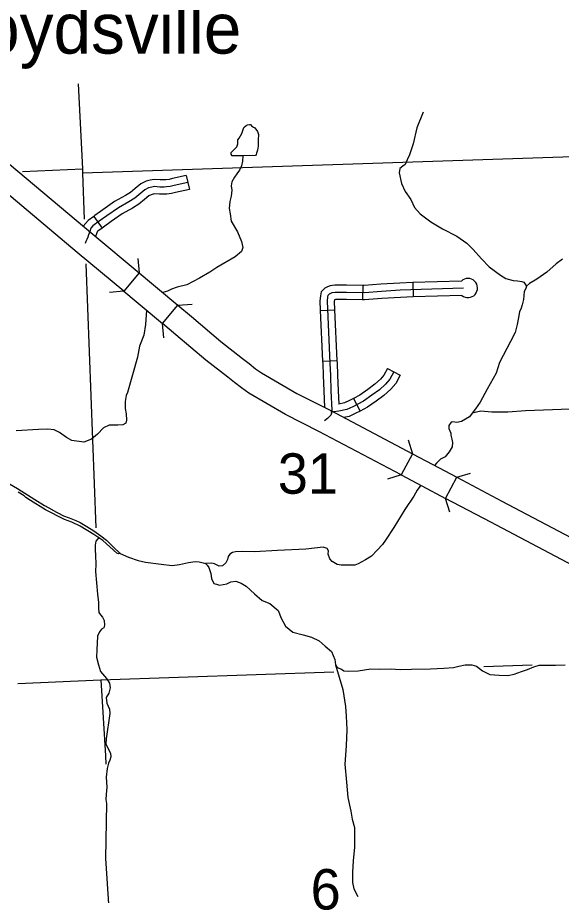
# Model space of a CAD drawing. Extents: x -5566 to 1759129, y -3726 to 731467.
# Drawn here: x -4657.8 to -4614.7, y 261.2 to 330.8 of the extents above; entities that cross this region are included whole.
import ezdxf

# ---------------------------------------------------------------- set-up
doc = ezdxf.new("R2010")
doc.units = 0
doc.layers.add('Default', color=7, linetype='Continuous')

msp = doc.modelspace()

# ---------------------------------------------------------------- linework, layer by layer
at = {"layer": 'Default'}
for p, q in [((-4644.471, 318.303), (-4644.22, 317.191)), ((-4651.807, 315.061), (-4651.133, 314.142)), ((-4630.479, 309.585), (-4630.494, 308.446)), ((-4626.502, 309.81), (-4626.466, 308.671)), ((-4633.838, 307.595), (-4632.7, 307.646)), ((-4633.659, 303.589), (-4632.521, 303.64)), ((-4628.501, 303.008), (-4627.5, 302.464)), ((-4631.212, 300.628), (-4630.685, 299.619))]:
    msp.add_line(p, q, dxfattribs=at)
for points in [[(-4653.033, 325.568), (-4652.708, 318.841), (-4652.694, 318.485), (-4652.558, 314.851)], [(-4625.686, 323.321), (-4626.173, 322.099), (-4626.469, 320.823), (-4626.756, 319.959), (-4626.954, 319.556), (-4627.122, 319.176), (-4627.285, 319.049), (-4627.521, 318.865), (-4627.577, 318.52), (-4627.409, 317.665), (-4627.112, 317.028), (-4626.672, 316.403), (-4626.376, 315.781), (-4625.917, 315.272), (-4625.067, 314.632), (-4624.143, 314.086), (-4623.021, 313.494), (-4622.227, 312.943), (-4621.73, 312.443), (-4621.058, 311.698), (-4620.436, 311.061), (-4619.547, 310.407), (-4619.13, 310.148), (-4618.554, 309.986), (-4618.202, 309.959), (-4617.866, 309.887), (-4617.704, 309.852), (-4617.475, 309.523)], [(-4640.457, 320.586), (-4640.378, 320.809), (-4640.391, 320.954), (-4640.391, 321.125), (-4640.286, 321.269), (-4640.049, 321.637), (-4639.892, 322.11), (-4639.721, 322.281), (-4639.603, 322.321), (-4639.458, 322.36), (-4639.366, 322.36), (-4639.288, 322.255), (-4639.13, 322.137), (-4639.038, 322.084), (-4638.828, 321.795), (-4638.749, 321.558), (-4638.762, 321.138)], [(-4638.762, 321.138), (-4638.762, 320.638), (-4638.828, 320.323), (-4638.893, 320.073), (-4638.92, 319.968), (-4638.985, 319.902), (-4639.971, 319.876), (-4640.825, 319.863), (-4640.917, 320.008), (-4640.917, 320.139), (-4640.68, 320.362), (-4640.457, 320.586)], [(-4613.817, 319.783), (-4652.694, 318.485)], [(-4639.971, 319.876), (-4640.007, 319.443), (-4640.092, 319.074), (-4640.247, 318.741), (-4640.464, 318.428), (-4640.645, 318.185), (-4640.851, 317.812), (-4640.908, 317.498), (-4640.865, 317.141), (-4640.916, 316.659), (-4641.022, 316.236), (-4641.055, 315.694), (-4640.979, 315.262), (-4640.912, 314.693), (-4640.418, 313.834), (-4640.086, 313.061), (-4639.986, 312.6), (-4640.096, 312.283), (-4640.597, 311.869), (-4642.053, 311.001), (-4642.602, 310.646), (-4643.412, 310.167), (-4644.426, 309.642), (-4645.2, 309.447), (-4645.643, 309.301), (-4645.956, 309.145), (-4646.336, 309.026)], [(-4658.494, 319.208), (-4651.889, 313.649), (-4648.215, 310.59)], [(-4657.461, 318.617), (-4652.708, 318.841)], [(-4644.471, 318.303), (-4645.557, 318.058), (-4645.836, 317.996), (-4646.088, 317.965), (-4646.237, 317.96), (-4646.538, 317.962), (-4647.002, 317.994), (-4647.32, 317.944), (-4647.659, 317.854), (-4648.073, 317.639), (-4648.513, 317.271)], [(-4648.215, 310.59), (-4649.43, 309.131), (-4653.107, 312.194), (-4659.717, 317.756)], [(-4644.346, 317.747), (-4645.433, 317.502), (-4645.739, 317.434), (-4646.044, 317.396), (-4646.23, 317.391), (-4646.56, 317.393), (-4646.976, 317.422), (-4647.203, 317.386), (-4647.453, 317.32), (-4647.755, 317.162), (-4648.55, 316.498), (-4649.011, 316.218), (-4649.85, 315.749), (-4650.757, 315.119), (-4651.374, 314.672), (-4651.871, 314.308), (-4652.026, 314.129), (-4652.122, 313.878), (-4652.211, 313.591), (-4652.271, 313.429), (-4652.347, 313.222), (-4652.426, 313.065), (-4652.498, 312.922)], [(-4648.513, 317.271), (-4648.882, 316.963), (-4649.298, 316.71), (-4650.153, 316.233), (-4651.086, 315.583), (-4651.709, 315.132), (-4651.807, 315.061)], [(-4644.22, 317.191), (-4645.309, 316.946), (-4645.642, 316.872), (-4646, 316.828), (-4646.223, 316.821), (-4646.582, 316.823), (-4646.951, 316.849), (-4647.085, 316.828), (-4647.246, 316.785), (-4647.437, 316.686), (-4647.783, 316.397)], [(-4647.783, 316.397), (-4648.217, 316.034), (-4648.725, 315.726), (-4649.548, 315.266), (-4650.427, 314.654), (-4651.039, 314.211), (-4651.133, 314.142)], [(-4651.807, 315.061), (-4652.259, 314.729), (-4652.644, 314.285)], [(-4651.133, 314.142), (-4651.482, 313.886), (-4651.53, 313.832), (-4651.583, 313.691), (-4651.657, 313.456)], [(-4652.423, 311.288), (-4651.635, 290.355)], [(-4648.319, 311.724), (-4648.215, 310.59)], [(-4614.632, 311.665), (-4615.123, 311.303), (-4615.876, 310.652), (-4616.668, 310.09), (-4617.255, 309.729), (-4617.475, 309.523), (-4617.551, 309.333), (-4617.664, 309.101), (-4617.722, 308.483), (-4617.825, 308.057), (-4617.906, 307.796), (-4618.039, 307.494), (-4618.131, 307.044), (-4618.217, 306.477), (-4618.381, 305.858), (-4618.769, 305.134), (-4619.635, 303.464), (-4619.894, 302.637), (-4620.599, 301.372), (-4621.175, 300.322), (-4621.536, 299.813), (-4621.804, 299.453), (-4621.997, 299.165), (-4622.629, 298.797), (-4623.006, 298.718), (-4623.339, 298.77), (-4623.453, 298.744), (-4623.637, 298.489)], [(-4648.215, 310.59), (-4647.235, 309.773), (-4646.751, 309.375), (-4645.135, 308.017)], [(-4622.654, 309.934), (-4626.502, 309.81)], [(-4630.479, 309.585), (-4631.749, 309.602), (-4632.367, 309.609), (-4632.697, 309.602), (-4633.056, 309.565), (-4633.268, 309.476), (-4633.487, 309.373), (-4633.77, 309.071), (-4633.833, 308.755), (-4633.872, 308.356), (-4633.838, 307.595)], [(-4622.476, 309.369), (-4627.496, 309.208), (-4628.996, 309.117), (-4630.347, 309.014), (-4631.756, 309.033), (-4632.364, 309.04), (-4632.661, 309.033), (-4632.914, 309.007), (-4633.036, 308.956), (-4633.146, 308.904), (-4633.243, 308.8), (-4633.269, 308.671), (-4633.301, 308.341), (-4633.082, 303.426), (-4633.043, 302.456), (-4632.991, 301.241), (-4632.926, 299.702), (-4632.946, 299.449), (-4632.991, 299.307), (-4633.079, 299.207), (-4633.273, 299.046), (-4633.508, 298.841)], [(-4626.502, 309.81), (-4627.523, 309.777), (-4629.035, 309.686), (-4630.365, 309.584), (-4630.479, 309.585)], [(-4649.43, 309.131), (-4650.565, 309.028)], [(-4649.43, 309.131), (-4648.446, 308.31), (-4647.965, 307.915), (-4646.357, 306.563)], [(-4630.494, 308.446), (-4631.763, 308.463), (-4632.361, 308.47), (-4632.626, 308.464), (-4632.718, 308.455), (-4632.731, 308.326), (-4632.7, 307.646)], [(-4626.466, 308.671), (-4627.47, 308.639), (-4628.957, 308.549), (-4630.329, 308.444), (-4630.494, 308.446)], [(-4622.614, 308.795), (-4626.466, 308.671)], [(-4646.357, 306.563), (-4645.135, 308.017), (-4644.06, 307.113), (-4641.727, 305.146), (-4640.01, 303.798), (-4639.48, 303.384), (-4638.968, 302.986), (-4638.49, 302.648), (-4635.691, 301.027), (-4633.07, 299.684), (-4626.538, 296.241), (-4627.423, 294.562)], [(-4645.135, 308.017), (-4644, 308.115)], [(-4647.626, 307.63), (-4647.69, 306.499), (-4647.833, 305.648), (-4648.166, 304.771), (-4648.336, 303.888), (-4649.138, 301.1), (-4649.231, 300.864), (-4649.32, 300.389), (-4649.314, 299.825), (-4649.223, 299.409), (-4649.197, 298.899), (-4649.272, 298.66), (-4649.51, 298.53), (-4649.889, 298.516), (-4650.595, 298.513), (-4651.035, 298.292), (-4651.51, 297.802), (-4651.974, 297.404), (-4652.588, 297.161), (-4653.534, 297.294), (-4653.96, 297.515), (-4654.521, 297.93), (-4654.946, 298.128), (-4655.442, 298.19), (-4656.186, 298.17), (-4657.966, 298.048)], [(-4633.838, 307.595), (-4633.659, 303.589)], [(-4632.7, 307.646), (-4632.521, 303.64)], [(-4627.423, 294.562), (-4633.946, 297.999), (-4636.6, 299.359), (-4639.516, 301.049), (-4640.099, 301.461), (-4640.647, 301.887), (-4641.18, 302.303), (-4642.925, 303.673), (-4645.283, 305.661), (-4646.357, 306.563)], [(-4646.259, 305.428), (-4646.357, 306.563)], [(-4633.659, 303.589), (-4633.651, 303.402), (-4633.612, 302.433), (-4633.56, 301.217), (-4633.505, 299.906)], [(-4632.521, 303.64), (-4632.513, 303.451), (-4632.474, 302.48), (-4632.422, 301.265), (-4632.377, 300.183)], [(-4628.501, 303.008), (-4628.795, 302.467), (-4629.067, 302.153), (-4629.511, 301.755), (-4630.08, 301.335), (-4630.703, 300.895), (-4631.212, 300.628)], [(-4628.001, 302.736), (-4628.324, 302.141), (-4628.66, 301.753), (-4629.151, 301.313), (-4629.746, 300.873), (-4630.405, 300.408), (-4631.272, 299.955), (-4631.724, 299.735), (-4632.358, 299.606), (-4632.771, 299.567), (-4632.991, 299.548)], [(-4627.5, 302.464), (-4627.853, 301.815), (-4628.253, 301.352), (-4628.791, 300.871), (-4629.412, 300.412), (-4630.108, 299.92), (-4630.685, 299.619)], [(-4631.212, 300.628), (-4631.528, 300.464), (-4631.908, 300.279), (-4632.377, 300.183)], [(-4630.685, 299.619), (-4631.015, 299.446), (-4631.54, 299.191), (-4631.97, 299.104)], [(-4612.601, 299.823), (-4617.567, 299.637), (-4618.971, 299.542), (-4619.69, 299.525), (-4620.234, 299.525), (-4621.112, 299.615), (-4621.804, 299.453)], [(-4623.637, 298.489), (-4623.637, 298.244), (-4623.479, 297.875), (-4623.497, 297.717), (-4623.4, 297.405), (-4623.368, 297.139), (-4623.378, 296.785), (-4623.63, 296.384), (-4623.935, 296), (-4624.309, 295.815), (-4624.636, 295.487), (-4624.774, 295.311)], [(-4626.875, 297.329), (-4626.538, 296.241)], [(-4626.538, 296.241), (-4624.904, 295.38), (-4623.012, 294.377)], [(-4661.41, 295.616), (-4660.163, 294.801), (-4657.844, 293.485)], [(-4627.423, 294.562), (-4628.512, 294.225)], [(-4627.423, 294.562), (-4625.791, 293.702), (-4623.901, 292.699)], [(-4623.012, 294.377), (-4621.923, 294.711)], [(-4595.073, 281.248), (-4595.087, 279.35), (-4595.451, 279.352), (-4596.296, 279.328), (-4597.053, 279.371), (-4597.723, 279.461), (-4598.724, 279.631), (-4598.995, 279.743), (-4599.363, 279.865), (-4600.547, 280.405), (-4611.583, 286.139), (-4612.869, 286.86), (-4620.322, 290.802), (-4623.901, 292.699), (-4623.012, 294.377)], [(-4623.012, 294.377), (-4619.434, 292.48), (-4611.96, 288.528), (-4610.68, 287.81), (-4599.715, 282.112), (-4598.669, 281.635), (-4598.331, 281.523), (-4598.194, 281.466), (-4597.439, 281.338), (-4596.873, 281.263), (-4596.269, 281.228), (-4595.471, 281.251), (-4595.073, 281.248)], [(-4657.844, 293.485), (-4656.477, 292.616), (-4655.707, 292.139), (-4655.081, 291.779)], [(-4649.689, 288.317), (-4649.848, 288.309), (-4649.975, 288.36), (-4651.08, 289.351), (-4651.791, 289.834), (-4652.883, 290.507), (-4653.531, 290.812), (-4654.128, 291.015), (-4655.639, 291.803), (-4656.833, 292.527), (-4657.183, 292.779), (-4657.331, 292.888), (-4657.81, 293.187)], [(-4625.875, 293.746), (-4626.145, 293.359), (-4626.431, 292.869), (-4627.129, 291.815), (-4628.018, 290.388), (-4628.665, 289.389), (-4628.91, 289.037), (-4629.326, 288.58), (-4629.773, 288.114), (-4630.256, 287.83), (-4630.829, 287.52), (-4631.106, 287.403), (-4631.447, 287.399), (-4631.789, 287.409), (-4632.176, 287.403), (-4632.505, 287.459), (-4632.885, 287.705), (-4633.075, 287.911), (-4633.217, 288.272), (-4633.196, 288.532), (-4633.294, 288.719), (-4633.617, 288.822), (-4634.993, 288.681), (-4637.236, 288.569), (-4639.047, 288.458), (-4640.019, 288.484), (-4640.565, 288.449), (-4640.806, 288.402), (-4641.006, 288.273), (-4641.136, 288.085), (-4641.196, 287.847), (-4641.323, 287.591), (-4641.587, 287.345), (-4641.852, 287.313), (-4642.076, 287.426), (-4642.216, 287.513), (-4642.446, 287.566), (-4642.942, 287.533)], [(-4623.567, 291.611), (-4623.901, 292.699)], [(-4655.108, 291.795), (-4654.204, 291.32), (-4653.747, 291.168), (-4653.223, 290.951), (-4652.883, 290.774), (-4652.363, 290.469), (-4651.804, 290.113), (-4651.233, 289.719), (-4650.796, 289.374), (-4650.243, 288.818), (-4649.71, 288.324)], [(-4651.364, 289.614), (-4651.634, 289.315), (-4651.699, 289), (-4651.7, 288.619), (-4651.661, 288.155), (-4651.629, 287.493), (-4651.653, 286.906), (-4651.512, 285.112), (-4651.441, 284.429), (-4651.433, 283.994), (-4651.398, 283.653), (-4651.269, 283.452), (-4651.111, 283.267), (-4650.98, 283.005), (-4650.956, 282.634), (-4651.005, 282.424), (-4651.178, 282.313), (-4651.346, 282.116), (-4651.511, 281.77), (-4651.548, 280.684), (-4651.597, 280.104), (-4651.425, 279.486), (-4651.264, 278.98), (-4650.793, 278.401), (-4650.548, 278.031), (-4650.511, 277.661), (-4650.598, 277.241), (-4650.82, 276.908), (-4650.758, 276.451), (-4650.548, 275.97), (-4650.524, 275.649), (-4650.829, 273.617), (-4650.857, 273.218), (-4650.746, 272.983), (-4650.474, 272.502), (-4650.45, 272.205), (-4650.524, 271.946), (-4650.635, 271.699), (-4650.746, 271.28), (-4650.82, 270.576), (-4650.761, 269.784), (-4650.833, 269.214), (-4650.853, 268.817), (-4650.783, 268.503), (-4650.863, 264.146), (-4650.596, 260.146)], [(-4649.71, 288.324), (-4649.048, 288.03), (-4648.286, 287.776), (-4647.701, 287.651), (-4646.453, 287.476), (-4645.578, 287.383), (-4645.009, 287.445), (-4644.301, 287.6), (-4643.769, 287.695), (-4643.447, 287.659), (-4643.121, 287.594), (-4642.942, 287.533), (-4642.808, 287.401), (-4642.686, 287.219), (-4642.522, 286.753), (-4642.473, 286.339), (-4642.278, 285.951), (-4642.06, 285.896), (-4641.834, 285.808), (-4641.263, 285.913), (-4640.926, 286.074), (-4640.542, 286.14), (-4640.125, 285.973), (-4639.722, 285.728), (-4639.07, 285.119), (-4638.44, 284.606), (-4637.835, 284.363), (-4637.192, 283.807), (-4636.948, 283.207), (-4636.597, 282.564), (-4636.026, 282.074), (-4635.209, 281.887), (-4634.533, 281.689), (-4633.934, 281.394), (-4633.443, 280.973), (-4632.939, 280.564), (-4632.686, 279.915), (-4632.624, 279.483), (-4632.055, 277.528), (-4631.834, 276.2), (-4631.797, 275.426), (-4631.741, 274.357), (-4631.778, 273.067), (-4631.889, 271.613), (-4631.76, 270.201), (-4631.668, 268.984), (-4631.41, 267.878), (-4631.299, 267.252), (-4631.133, 266.606), (-4631.115, 265.851), (-4631.115, 265.027), (-4631.229, 263.953), (-4631.287, 263.043), (-4631.287, 262.221), (-4631.184, 261.72), (-4630.861, 261.117)], [(-4632.624, 279.483), (-4632.493, 279.272), (-4632.169, 279.154), (-4631.984, 279.019), (-4631.619, 278.986), (-4630.839, 279.021), (-4629.825, 279.168), (-4629.144, 279.15), (-4628.282, 279.176), (-4627.485, 279.131), (-4626.61, 279.156), (-4625.105, 279.167), (-4624.044, 279.221), (-4623.272, 279.287), (-4622.858, 279.386), (-4622.353, 279.495), (-4621.815, 279.5), (-4621.446, 279.383), (-4620.968, 279.032), (-4620.394, 278.742), (-4619.652, 278.686), (-4618.967, 278.65), (-4618.459, 278.753), (-4617.896, 278.97), (-4617.419, 279.126), (-4616.91, 279.344), (-4616.492, 279.467), (-4615.198, 279.458), (-4614.427, 279.484)], [(-4620.881, 279.367), (-4617.047, 279.501)], [(-4651.238, 278.299), (-4632.765, 278.949)], [(-4657.829, 278.025), (-4651.238, 278.299)], [(-4651.238, 278.299), (-4650.863, 272.275), (-4650.834, 271.613)]]:
    msp.add_lwpolyline(points, dxfattribs=at)
msp.add_arc((-4622.132, 309.382), 0.759, 230.60975, 133.42863, dxfattribs=at)

# ---------------------------------------------------------------- texts
for s, height, p in [('Boydsville', 4.0097, (-4664.237, 327.974)), ('31', 3.2048, (-4637.206, 293.066)), ('6', 3.208, (-4634.606, 260.088))]:
    msp.add_text(s, height=height, dxfattribs=at).set_placement(p)

doc.saveas('drawing.dxf')
